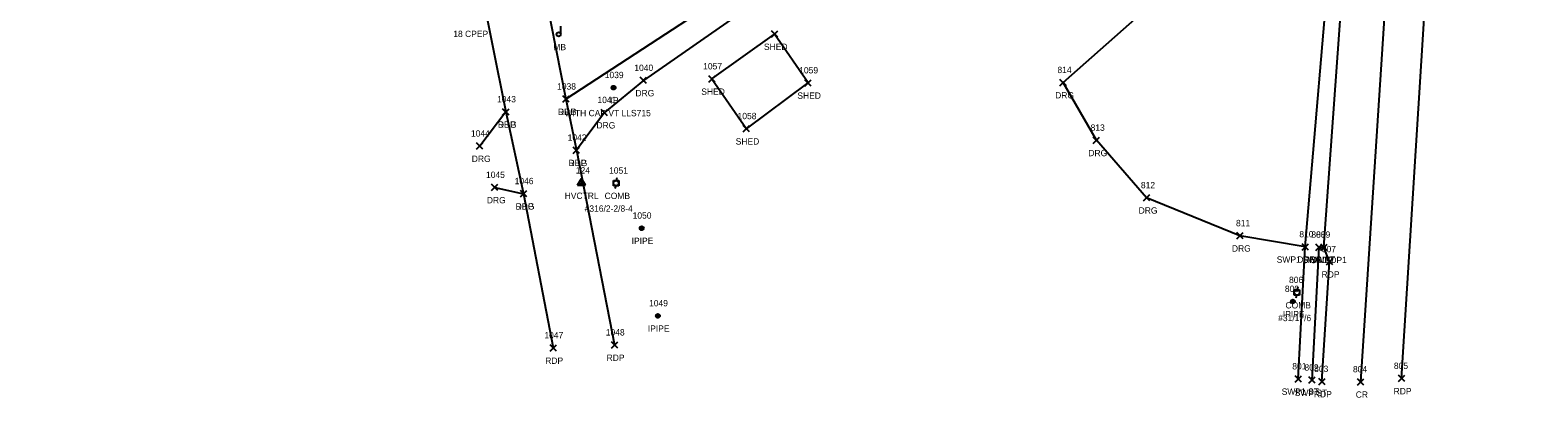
# Model space of a CAD drawing. Extents: x 1615599 to 1619911, y 273782 to 280437.
# Drawn here: x 1616094.4 to 1616569.8, y 279473.7 to 279589.5 of the extents above; entities that cross this region are included whole.
import ezdxf

# ---------------------------------------------------------------- set-up
doc = ezdxf.new("R2010")
doc.units = 0
for name, color, linetype in [('C_A', 7, 'Continuous'), ('C_I', 7, 'Continuous'), ('CPSM', 7, 'Continuous'), ('D_C', 7, 'Continuous'), ('L_A', 7, 'Continuous'), ('L_I', 7, 'Continuous'), ('L_TIC', 7, 'Continuous'), ('LBC', 7, 'Continuous'), ('LMB', 7, 'Continuous'), ('M_A', 7, 'Continuous'), ('M_C', 7, 'Continuous'), ('M_I', 7, 'Continuous'), ('MPIP', 7, 'Continuous'), ('MPIR', 7, 'Continuous'), ('P_A', 7, 'Continuous'), ('P_I', 7, 'Continuous'), ('P_TIC', 7, 'Continuous'), ('PET', 7, 'Continuous'), ('PRC', 7, 'Continuous'), ('R_A', 7, 'Continuous'), ('R_I', 7, 'Continuous'), ('R_TIC', 7, 'Continuous'), ('RDG', 7, 'Continuous'), ('RSW', 7, 'Continuous'), ('U_A', 7, 'Continuous'), ('U_C', 7, 'Continuous'), ('U_I', 7, 'Continuous'), ('UP', 7, 'Continuous')]:
    doc.layers.add(name, color=color, linetype=linetype)

msp = doc.modelspace()

# ---------------------------------------------------------------- linework, layer by layer
at = {"layer": 'CPSM'}
for p, q in [((1616267.01, 279540.62), (1616268.26, 279542.78)), ((1616267.01, 279540.62), (1616268.26, 279541.34)), ((1616267.01, 279540.62), (1616269.51, 279540.62)), ((1616269.51, 279540.62), (1616268.26, 279542.78)), ((1616268.26, 279541.34), (1616268.26, 279542.78)), ((1616268.26, 279541.34), (1616268.26, 279541.34)), ((1616268.26, 279541.34), (1616269.51, 279540.62))]:
    msp.add_line(p, q, dxfattribs=at)
at = {"layer": 'L_TIC'}
for points in [[(1616328.15, 279587.28), (1616330.15, 279589.28)], [(1616330.15, 279587.28), (1616328.15, 279589.28)], [(1616328.15, 279587.28), (1616330.15, 279589.28)], [(1616330.15, 279587.28), (1616328.15, 279589.28)], [(1616308.39, 279573.14), (1616310.39, 279575.14)], [(1616310.39, 279573.14), (1616308.39, 279575.14)], [(1616308.39, 279573.14), (1616310.39, 279575.14)], [(1616310.39, 279573.14), (1616308.39, 279575.14)], [(1616338.68, 279571.88), (1616340.68, 279573.88)], [(1616340.68, 279571.88), (1616338.68, 279573.88)], [(1616319.24, 279557.46), (1616321.24, 279559.46)], [(1616321.24, 279557.46), (1616319.24, 279559.46)]]:
    msp.add_lwpolyline(points, dxfattribs=at)
at = {"layer": 'LBC'}
for points in [[(1616309.39, 279574.14), (1616320.24, 279558.46), (1616339.68, 279572.88), (1616329.15, 279588.28)], [(1616309.39, 279574.14), (1616329.15, 279588.28)]]:
    msp.add_lwpolyline(points, dxfattribs=at)
at = {"layer": 'LMB'}
for p, q in [((1616261.06, 279588.2), (1616261.06, 279588.2)), ((1616261.72, 279588.21), (1616261.72, 279590.81))]:
    msp.add_line(p, q, dxfattribs=at)
msp.add_circle((1616261.06, 279588.2), 0.656, dxfattribs=at)
at = {"layer": 'MPIP'}
for centre, radius in [((1616287.23, 279527.11), 0.625), ((1616287.23, 279527.11), 0.0833), ((1616492.58, 279504.01), 0.625), ((1616492.58, 279504.01), 0.0833), ((1616292.34, 279499.48), 0.625), ((1616292.34, 279499.48), 0.0833)]:
    msp.add_circle(centre, radius, dxfattribs=at)
at = {"layer": 'MPIR'}
for radius in [0.625, 0.0833]:
    msp.add_circle((1616278.36, 279571.39), radius, dxfattribs=at)
at = {"layer": 'P_TIC'}
for points in [[(1616262.33, 279566.8), (1616264.33, 279568.8)], [(1616264.33, 279566.8), (1616262.33, 279568.8)], [(1616243.39, 279562.76), (1616245.39, 279564.76)], [(1616245.39, 279562.76), (1616243.39, 279564.76)], [(1616265.66, 279550.67), (1616267.66, 279552.67)], [(1616267.66, 279550.67), (1616265.66, 279552.67)], [(1616248.99, 279536.98), (1616250.99, 279538.98)], [(1616250.99, 279536.98), (1616248.99, 279538.98)], [(1616501.36, 279520.09), (1616503.36, 279522.09)], [(1616503.36, 279520.09), (1616501.36, 279522.09)], [(1616503.15, 279515.53), (1616505.15, 279517.53)], [(1616505.15, 279515.53), (1616503.15, 279517.53)], [(1616258.32, 279488.36), (1616260.32, 279490.36)], [(1616260.32, 279488.36), (1616258.32, 279490.36)], [(1616277.68, 279489.29), (1616279.68, 279491.29)], [(1616279.68, 279489.29), (1616277.68, 279491.29)], [(1616500.73, 279477.79), (1616502.73, 279479.79)], [(1616502.73, 279477.79), (1616500.73, 279479.79)], [(1616512.97, 279477.68), (1616514.97, 279479.68)], [(1616514.97, 279477.68), (1616512.97, 279479.68)], [(1616525.87, 279478.75), (1616527.87, 279480.75)], [(1616527.87, 279478.75), (1616525.87, 279480.75)]]:
    msp.add_lwpolyline(points, dxfattribs=at)
at = {"layer": 'PET'}
for points in [[(1616094.39, 280432.05), (1616095.97, 280416.03), (1616096.35, 280407.62), (1616112.28, 280298.8), (1616113.01, 280288.09), (1616121.62, 280240.92), (1616154.97, 280052.02), (1616164.78, 279993.49), (1616191.14, 279842.72), (1616209.73, 279742.75), (1616231.48, 279628.16), (1616244.39, 279563.76), (1616249.99, 279537.98), (1616259.32, 279489.36)], [(1616116.33, 280409.22), (1616122.66, 280382.08), (1616122.16, 280374.78), (1616121.96, 280362.12), (1616140.8, 280248.09), (1616148.4, 280204.31), (1616173.58, 280057.29), (1616184.77, 279993.13), (1616204.83, 279881.25), (1616210.2, 279851.21), (1616228.38, 279746.88), (1616250.76, 279631.19), (1616263.33, 279567.8), (1616266.66, 279551.67), (1616278.68, 279490.29)], [(1616501.73, 279478.79), (1616504.15, 279516.53), (1616502.36, 279521.09), (1616509.74, 279623.18), (1616513.26, 279680.58), (1616517.86, 279738.11), (1616521.66, 279796.02), (1616535.31, 279880.04), (1616539.68, 279905.35), (1616550.57, 279973.08)], [(1616526.87, 279479.75), (1616534.9, 279608.29), (1616540.12, 279681.26), (1616545.34, 279739.77), (1616548.4, 279773.98), (1616552.49, 279810.18), (1616554.63, 279819.12), (1616562.79, 279830.13), (1616562.2, 279831.59), (1616577.14, 279852.75), (1616589.88, 279863.08), (1616620.87, 279876.82)]]:
    msp.add_lwpolyline(points, dxfattribs=at)
at = {"layer": 'PRC'}
msp.add_lwpolyline([(1616513.97, 279478.68), (1616523.34, 279622.43), (1616526.18, 279679.14), (1616531, 279739.46), (1616538.76, 279812.35), (1616562.87, 279952.64)], dxfattribs=at)
at = {"layer": 'R_TIC'}
for points in [[(1616286.77, 279572.66), (1616288.77, 279574.66)], [(1616288.77, 279572.66), (1616286.77, 279574.66)], [(1616419.14, 279571.99), (1616421.14, 279573.99)], [(1616421.14, 279571.99), (1616419.14, 279573.99)], [(1616262.33, 279566.8), (1616264.33, 279568.8)], [(1616264.33, 279566.8), (1616262.33, 279568.8)], [(1616243.39, 279562.76), (1616245.39, 279564.76)], [(1616245.39, 279562.76), (1616243.39, 279564.76)], [(1616274.48, 279562.53), (1616276.48, 279564.53)], [(1616276.48, 279562.53), (1616274.48, 279564.53)], [(1616429.6, 279553.8), (1616431.6, 279555.8)], [(1616431.6, 279553.8), (1616429.6, 279555.8)], [(1616235.17, 279551.99), (1616237.17, 279553.99)], [(1616237.17, 279551.99), (1616235.17, 279553.99)], [(1616265.66, 279550.67), (1616267.66, 279552.67)], [(1616267.66, 279550.67), (1616265.66, 279552.67)], [(1616239.91, 279538.95), (1616241.91, 279540.95)], [(1616241.91, 279538.95), (1616239.91, 279540.95)], [(1616248.99, 279536.98), (1616250.99, 279538.98)], [(1616250.99, 279536.98), (1616248.99, 279538.98)], [(1616445.46, 279535.69), (1616447.46, 279537.69)], [(1616447.46, 279535.69), (1616445.46, 279537.69)], [(1616474.87, 279523.73), (1616476.87, 279525.73)], [(1616476.87, 279523.73), (1616474.87, 279525.73)], [(1616495.49, 279520.23), (1616497.49, 279522.23)], [(1616497.49, 279520.23), (1616495.49, 279522.23)], [(1616495.49, 279520.23), (1616497.49, 279522.23)], [(1616497.49, 279520.23), (1616495.49, 279522.23)], [(1616499.86, 279520.09), (1616501.86, 279522.09)], [(1616501.86, 279520.09), (1616499.86, 279522.09)], [(1616501.36, 279520.09), (1616503.36, 279522.09)], [(1616503.36, 279520.09), (1616501.36, 279522.09)], [(1616493.27, 279478.6), (1616495.27, 279480.6)], [(1616495.27, 279478.6), (1616493.27, 279480.6)], [(1616497.66, 279478.23), (1616499.66, 279480.23)], [(1616499.66, 279478.23), (1616497.66, 279480.23)]]:
    msp.add_lwpolyline(points, dxfattribs=at)
at = {"layer": 'RDG'}
for points in [[(1616476.4, 279764.58), (1616476.92, 279750.96), (1616468.44, 279740.89), (1616429.63, 279704.65), (1616403.63, 279679.78), (1616362.98, 279636.29), (1616328.32, 279610.24), (1616263.33, 279567.8)], [(1616497.87, 279749.53), (1616489.21, 279745.16), (1616480.11, 279737.82), (1616436.78, 279696.31), (1616411.24, 279672.61), (1616387.47, 279642.06), (1616397.28, 279621.61), (1616371.82, 279603.44), (1616356.02, 279618.85), (1616332.01, 279604.55), (1616287.77, 279573.66), (1616275.48, 279563.53), (1616266.66, 279551.67)], [(1616496.49, 279521.23), (1616475.87, 279524.73), (1616446.46, 279536.69), (1616430.6, 279554.8), (1616420.14, 279572.99), (1616452.75, 279601.95), (1616486.09, 279622.02), (1616505.13, 279623.42)], [(1616244.39, 279563.76), (1616236.17, 279552.99)], [(1616240.91, 279539.95), (1616249.99, 279537.98)]]:
    msp.add_lwpolyline(points, dxfattribs=at)
at = {"layer": 'RSW'}
for points in [[(1616494.27, 279479.6), (1616496.49, 279521.23), (1616505.13, 279623.42), (1616508.3, 279681.06), (1616512.82, 279741.67)], [(1616498.66, 279479.23), (1616500.86, 279521.09), (1616502.36, 279521.09)]]:
    msp.add_lwpolyline(points, dxfattribs=at)
at = {"layer": 'UP'}
for p, q in [((1616278.32, 279540.46), (1616278.32, 279542.12)), ((1616278.32, 279542.12), (1616279.99, 279542.12)), ((1616279.99, 279540.46), (1616278.32, 279540.46)), ((1616278.91, 279539.62), (1616279.16, 279540.46)), ((1616279.41, 279542.96), (1616279.16, 279542.12)), ((1616279.16, 279541.29), (1616279.16, 279541.29)), ((1616279.99, 279542.12), (1616279.99, 279540.46)), ((1616493.03, 279505.99), (1616493.03, 279507.65)), ((1616493.03, 279507.65), (1616494.7, 279507.65)), ((1616494.11, 279508.49), (1616493.86, 279507.65)), ((1616494.7, 279507.65), (1616494.7, 279505.99)), ((1616494.7, 279505.99), (1616493.03, 279505.99)), ((1616493.61, 279505.15), (1616493.86, 279505.99)), ((1616493.86, 279506.82), (1616493.86, 279506.82))]:
    msp.add_line(p, q, dxfattribs=at)
for centre in [(1616279.16, 279541.29), (1616493.86, 279506.82)]:
    msp.add_circle(centre, 0.833, dxfattribs=at)

# ---------------------------------------------------------------- texts
at = {"layer": 'C_A'}
msp.add_text('HVCTRL', height=2, dxfattribs=at).set_placement((1616262.95, 279536.34))
at = {"layer": 'C_I'}
msp.add_text('124', height=2, dxfattribs=at).set_placement((1616266.46, 279544.34))
at = {"layer": 'D_C'}
msp.add_text('18 CPEP', height=2, dxfattribs=at).set_placement((1616227.82, 279587.34))
at = {"layer": 'L_A'}
for s, p in [('MB', (1616259.37, 279583.2)), ('SHED', (1616325.79, 279583.28)), ('SHED', (1616325.79, 279583.28)), ('SHED', (1616306.03, 279569.14)), ('SHED', (1616306.03, 279569.14)), ('SHED', (1616336.32, 279567.88)), ('SHED', (1616316.88, 279553.46))]:
    msp.add_text(s, height=2, dxfattribs=at).set_placement(p)
at = {"layer": 'L_I'}
for s, p in [('1057', (1616306.62, 279577.14)), ('1057', (1616306.62, 279577.14)), ('1059', (1616336.9, 279575.88)), ('1058', (1616317.47, 279561.46))]:
    msp.add_text(s, height=2, dxfattribs=at).set_placement(p)
at = {"layer": 'M_A'}
for s, p in [('IP', (1616277.4, 279566.39)), ('IPIPE', (1616284.07, 279522.11)), ('IPIPE', (1616489.42, 279499.01)), ('IPIPE', (1616289.18, 279494.48))]:
    msp.add_text(s, height=2, dxfattribs=at).set_placement(p)
at = {"layer": 'M_C'}
msp.add_text('WITH CAP VT LLS715', height=2, dxfattribs=at).set_placement((1616262.91, 279562.39))
at = {"layer": 'M_I'}
for s, p in [('1039', (1616275.58, 279574.39)), ('1050', (1616284.38, 279530.11)), ('800', (1616490.06, 279507.01)), ('1049', (1616289.56, 279502.48))]:
    msp.add_text(s, height=2, dxfattribs=at).set_placement(p)
at = {"layer": 'P_A'}
for s, p in [('RDP', (1616260.82, 279562.8)), ('RDP', (1616241.88, 279558.76)), ('RDP', (1616264.15, 279546.67)), ('RDP', (1616247.48, 279532.98)), ('RDP', (1616499.85, 279516.09)), ('RDP', (1616501.64, 279511.53)), ('RDP', (1616256.81, 279484.36)), ('RDP', (1616276.17, 279485.29)), ('RDP', (1616499.22, 279473.79)), ('CR', (1616512.4, 279473.68)), ('RDP', (1616524.36, 279474.75))]:
    msp.add_text(s, height=2, dxfattribs=at).set_placement(p)
at = {"layer": 'P_I'}
for s, p in [('1043', (1616241.62, 279566.76)), ('1038', (1616260.56, 279570.8)), ('1042', (1616263.89, 279554.67)), ('1046', (1616247.17, 279540.98)), ('809', (1616499.91, 279524.09)), ('807', (1616501.71, 279519.53)), ('1047', (1616256.55, 279492.36)), ('1048', (1616275.91, 279493.29)), ('803', (1616499.29, 279481.79)), ('804', (1616511.53, 279481.68)), ('805', (1616524.43, 279482.75))]:
    msp.add_text(s, height=2, dxfattribs=at).set_placement(p)
at = {"layer": 'R_A'}
for s, p in [('DRG', (1616285.26, 279568.66)), ('DRG', (1616417.62, 279567.99)), ('DRG', (1616260.82, 279562.8)), ('DRG', (1616241.88, 279558.76)), ('DRG', (1616272.97, 279558.53)), ('DRG', (1616233.65, 279547.99)), ('DRG', (1616428.08, 279549.8)), ('DRG', (1616264.15, 279546.67)), ('DRG', (1616238.4, 279534.95)), ('DRG', (1616247.48, 279532.98)), ('DRG', (1616443.94, 279531.69)), ('DRG', (1616473.36, 279519.73)), ('SWP1 DRG ST', (1616487.49, 279516.23)), ('DRG', (1616493.98, 279516.23)), ('SWP RDP1', (1616495.62, 279516.09)), ('SWP', (1616498.22, 279516.09)), ('SWP1 ST', (1616489.05, 279474.6)), ('SWP ST', (1616493.15, 279474.23))]:
    msp.add_text(s, height=2, dxfattribs=at).set_placement(p)
at = {"layer": 'R_I'}
for s, p in [('1040', (1616284.91, 279576.66)), ('814', (1616418.34, 279575.99)), ('1043', (1616241.62, 279566.76)), ('1038', (1616260.56, 279570.8)), ('1041', (1616273.28, 279566.53)), ('813', (1616428.8, 279557.8)), ('1044', (1616233.39, 279555.99)), ('1042', (1616263.89, 279554.67)), ('1045', (1616238.14, 279542.95)), ('1046', (1616247.17, 279540.98)), ('812', (1616444.66, 279539.69)), ('811', (1616474.64, 279527.73)), ('810', (1616494.61, 279524.23)), ('810', (1616494.61, 279524.23)), ('808', (1616498.41, 279524.09)), ('809', (1616499.91, 279524.09)), ('801', (1616492.39, 279482.6)), ('802', (1616496.22, 279482.23))]:
    msp.add_text(s, height=2, dxfattribs=at).set_placement(p)
at = {"layer": 'U_A'}
for p in [(1616275.54, 279536.29), (1616490.25, 279501.82)]:
    msp.add_text('COMB', height=2, dxfattribs=at).set_placement(p)
at = {"layer": 'U_C'}
for s, p in [('#316/2-2/8-4', (1616269.24, 279532.29)), ('#31/17/6', (1616487.94, 279497.82))]:
    msp.add_text(s, height=2, dxfattribs=at).set_placement(p)
at = {"layer": 'U_I'}
for s, p in [('1051', (1616276.95, 279544.29)), ('806', (1616491.37, 279509.82))]:
    msp.add_text(s, height=2, dxfattribs=at).set_placement(p)

doc.saveas('drawing.dxf')
